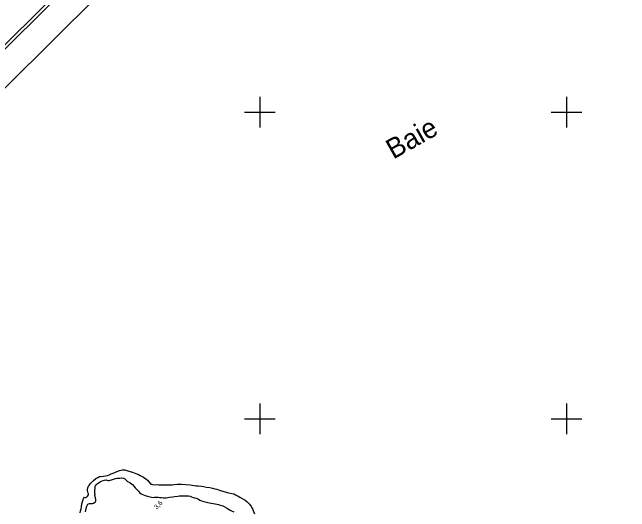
# Model space of a CAD drawing. Extents: x 381879 to 384696, y 5564785 to 5567594.
# Drawn here: x 382438.6 to 382841.1, y 5565939.6 to 5566265 of the extents above; entities that cross this region are included whole.
import ezdxf

# ---------------------------------------------------------------- set-up
doc = ezdxf.new("R2010")
doc.units = 0
for name, color, linetype in [('Niveau 2', 7, 'Continuous'), ('Niveau 3', 7, 'Continuous'), ('Niveau 4', 7, 'Continuous'), ('Niveau 60', 7, 'Continuous'), ('Niveau 61', 7, 'Continuous')]:
    doc.layers.add(name, color=color, linetype=linetype)

msp = doc.modelspace()

# ---------------------------------------------------------------- linework, layer by layer
at = {"layer": 'Niveau 2'}
msp.add_lwpolyline([(382486.31, 5565939.57), (382486.62, 5565940.56), (382486.81, 5565941.58), (382487.21, 5565943.11), (382487.58, 5565944.07), (382487.88, 5565944.52), (382488.36, 5565944.75), (382488.85, 5565944.86), (382489.9, 5565945), (382490.94, 5565944.96), (382491.46, 5565945.15), (382492.42, 5565945.68), (382492.8, 5565946.04), (382493.01, 5565946.51), (382493.11, 5565947.07), (382493.07, 5565947.57), (382492.8, 5565948.6), (382492.47, 5565950.14), (382492.53, 5565951.22), (382492.47, 5565951.72), (382492.42, 5565953.3), (382492.52, 5565954.83), (382492.68, 5565955.88), (382492.88, 5565956.37), (382493.44, 5565957.28), (382494.22, 5565958), (382495.13, 5565958.67), (382496.06, 5565959.22), (382497.1, 5565959.63), (382498.67, 5565960.07), (382499.68, 5565960.23), (382500.18, 5565960.1), (382501.18, 5565959.87), (382501.75, 5565959.89), (382502.3, 5565960.01), (382503.3, 5565960.37), (382505.9, 5565961.24), (382506.96, 5565961.41), (382508.03, 5565961.34), (382508.56, 5565961.42), (382510.08, 5565961.53), (382511.16, 5565961.36), (382511.68, 5565961.12), (382512.6, 5565960.42), (382513.28, 5565959.65), (382513.7, 5565959.34), (382515.11, 5565958.49), (382516.45, 5565957.6), (382516.84, 5565957.19), (382518.74, 5565955.2), (382520.66, 5565953.17), (382521.72, 5565951.94), (382522.56, 5565951.25), (382523.11, 5565951.03), (382524.11, 5565950.55), (382525.11, 5565950.18), (382526.64, 5565949.71), (382528.36, 5565949.26), (382529.44, 5565949.08), (382531.05, 5565948.92), (382531.57, 5565949.08), (382532.08, 5565949.11), (382533.7, 5565949.04), (382534.82, 5565948.86), (382535.94, 5565948.77), (382537.11, 5565948.58), (382537.67, 5565948.65), (382538.84, 5565948.68), (382540.01, 5565948.88), (382541.1, 5565948.96), (382543.3, 5565949.2), (382544.31, 5565949.4), (382546.4, 5565949.73), (382547.46, 5565949.9), (382548, 5565949.94), (382549.55, 5565949.84), (382552.23, 5565949.88), (382553.4, 5565949.99), (382554.44, 5565949.78), (382555.45, 5565949.34), (382556.41, 5565948.87), (382557.48, 5565948.59), (382559.02, 5565948.13), (382559.99, 5565947.62), (382560.94, 5565947.12), (382561.91, 5565946.71), (382563.4, 5565946.28), (382566.07, 5565945.62), (382568.25, 5565945.12), (382570.88, 5565944.59), (382571.96, 5565944.51), (382573.06, 5565944.25), (382574.12, 5565943.88), (382575.75, 5565943.37), (382576.74, 5565942.89), (382578.19, 5565942.01), (382579.54, 5565941.12), (382580.56, 5565940.61), (382581.58, 5565940.21), (382582.99, 5565939.52)], dxfattribs=at)
at = {"layer": 'Niveau 4'}
for points in [[(382482.79, 5565938.9), (382483.11, 5565940.03), (382483.41, 5565941.38), (382483.62, 5565942.69), (382484, 5565944.58), (382484.43, 5565945.91), (382485.08, 5565948.15), (382485.69, 5565949.01), (382486.21, 5565948.8), (382486.74, 5565948.83), (382487.25, 5565949.19), (382487.54, 5565949.64), (382488.25, 5565950.56), (382488.24, 5565951.1), (382488.06, 5565951.6), (382487.52, 5565953.43), (382487.53, 5565953.99), (382487.72, 5565955.07), (382488.2, 5565956.14), (382488.59, 5565956.69), (382489.36, 5565957.66), (382490.3, 5565958.64), (382491.4, 5565959.68), (382493.01, 5565961.15), (382494.23, 5565961.94), (382495.47, 5565962.44), (382496.18, 5565962.54), (382498.14, 5565962.76), (382500.63, 5565963.23), (382501.78, 5565963.67), (382503, 5565964.24), (382504.27, 5565964.76), (382505.91, 5565965.36), (382508.49, 5565966.3), (382510.2, 5565966.82), (382511.31, 5565966.92), (382511.97, 5565966.82), (382512.66, 5565966.59), (382514.51, 5565966.04), (382516.84, 5565965.31), (382517.96, 5565964.87), (382519.11, 5565964.54), (382520.85, 5565963.85), (382521.98, 5565963.21), (382524.12, 5565961.96), (382525.68, 5565960.98), (382526.65, 5565960.12), (382527.51, 5565959.11), (382528.85, 5565957.61), (382529.39, 5565957.4), (382529.95, 5565957.31), (382531.71, 5565957.14), (382532.95, 5565957.18)], [(382532.95, 5565957.18), (382534.15, 5565957.11), (382535.42, 5565957.1), (382538.49, 5565957.05), (382541.49, 5565957.04), (382542.79, 5565957.15), (382544.17, 5565957.34), (382546.09, 5565957.53), (382547.75, 5565957.57), (382548.93, 5565957.5), (382551.73, 5565957.27), (382554.53, 5565957.02), (382555.82, 5565956.84), (382558.43, 5565956.51), (382559.77, 5565956.42), (382561.95, 5565956.19), (382563.32, 5565955.98), (382565.2, 5565955.61), (382567.34, 5565955.25), (382569.21, 5565954.85), (382570.56, 5565954.49), (382571.85, 5565954.21), (382573.06, 5565953.79), (382574.99, 5565953.17), (382577.37, 5565952.45), (382578.62, 5565952.14), (382579.77, 5565951.95), (382581.75, 5565951.48), (382582.92, 5565951.12), (382584.07, 5565950.61), (382585.75, 5565949.78), (382586.85, 5565949.13), (382588.98, 5565948), (382590.51, 5565947.06), (382591.47, 5565946.24), (382592.36, 5565945.38), (382593.15, 5565944.44), (382594.25, 5565943.02), (382594.8, 5565942.12), (382595.42, 5565941.06), (382595.95, 5565939.79), (382596.56, 5565938.1)]]:
    msp.add_lwpolyline(points, dxfattribs=at)
at = {"layer": 'Niveau 60'}
msp.add_lwpolyline([(382780.54, 5564785.16), (381879.11, 5565693.82), (383794.51, 5567593.97), (384695.95, 5566685.3), (382780.55, 5564785.15)], dxfattribs=at)
for points in [[(381881.93, 5565693.86), (383794.53, 5567591.15), (384693.12, 5566685.31), (382780.52, 5564788.02)], [(383653.8, 5566971.92), (383426.67, 5567200.87), (383197.47, 5566973.49), (381907.4, 5565693.71), (382780.65, 5564813.45), (384299.92, 5566320.61)]]:
    msp.add_lwpolyline(points, close=True, dxfattribs=at)
at = {"layer": 'Niveau 61'}
for points in [[(382600, 5566210), (382600, 5566200), (382600, 5566190)], [(382800, 5566210), (382800, 5566200), (382800, 5566190)], [(382590, 5566200), (382600, 5566200), (382610, 5566200)], [(382790, 5566200), (382800, 5566200), (382810, 5566200)], [(382600, 5566010), (382600, 5566000), (382600, 5565990)], [(382800, 5566010), (382800, 5566000), (382800, 5565990)], [(382590, 5566000), (382600, 5566000), (382610, 5566000)], [(382790, 5566000), (382800, 5566000), (382810, 5566000)]]:
    msp.add_lwpolyline(points, dxfattribs=at)

# ---------------------------------------------------------------- texts
at = {"layer": 'Niveau 3'}
msp.add_text('3,6', height=3, rotation=44.7717, dxfattribs=at).set_placement((382532.71, 5565940.91))
at = {"layer": 'Niveau 4'}
msp.add_text('Baie', height=13, rotation=29.3612, dxfattribs=at).set_placement((382686.99, 5566168.97))

doc.saveas('drawing.dxf')
